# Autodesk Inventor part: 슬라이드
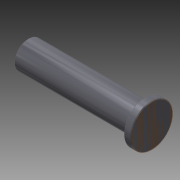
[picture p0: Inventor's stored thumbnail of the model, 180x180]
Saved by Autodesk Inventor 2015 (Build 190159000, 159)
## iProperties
Created: 2015-10
Part Number: 슬라이드
Document SubType Name: Modeling
Designer: mdu
Density: 7.86 g/cm^3
Material: 강철, 연강
Mass: 1603.27 g
Surface Area: 269.019 cm^2
Volume: 203.978 cm^3
Appearance: 강철 - 광택
Author: mdu
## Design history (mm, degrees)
sketch "스케치1"
  geometry: L1 (-75, 162)-(-75, 58) reference; L2 (-148, 110)-(22, 110); L3 (-148, 110)-(-148, 129); L4 (-148, 129)-(12, 129); L5 (12, 129)-(12, 139); L6 (12, 139)-(22, 139); L7 (22, 139)-(22, 110); 2 further points
  constraints: 12 end point, 3 parallel, 3 perpendicular, 1 midpoint, 1 point on line
  dimensions: "d0" = 58 diameter of L6 L2; "d1" = 38 diameter of L4 L2; "d2" = 10 distance of L5.end L6.end; "d3" = 170 distance of L2.start L2.end; "d4" = 73 distance between parallel lines of L3 L1
revolve "회전1" sketch "스케치1" stored, may be unused: angle "d5" = 90 deg
hole "구멍1" diameter "d11" = 13.376; stored, may be unused: countersink angle "d15" = 90 deg, drill point angle "d17" = 118 deg; dims "d9" = 10, "d10" = 10, "d12" = 22, "d13" = 4, "d14" = 2, "d16" = 25
chamfer "모따기1" distance "d6" = 1; stored, may be unused: second distance "d7" = 2, angle "d8" = 45 deg
sketch "스케치3"
  geometry: C1 r 29 at (0, 0) reference; 1 further point
feature "경계 패치2" sketch "스케치3"
node "솔리드1"
node "참조1"
node "곡면2"
